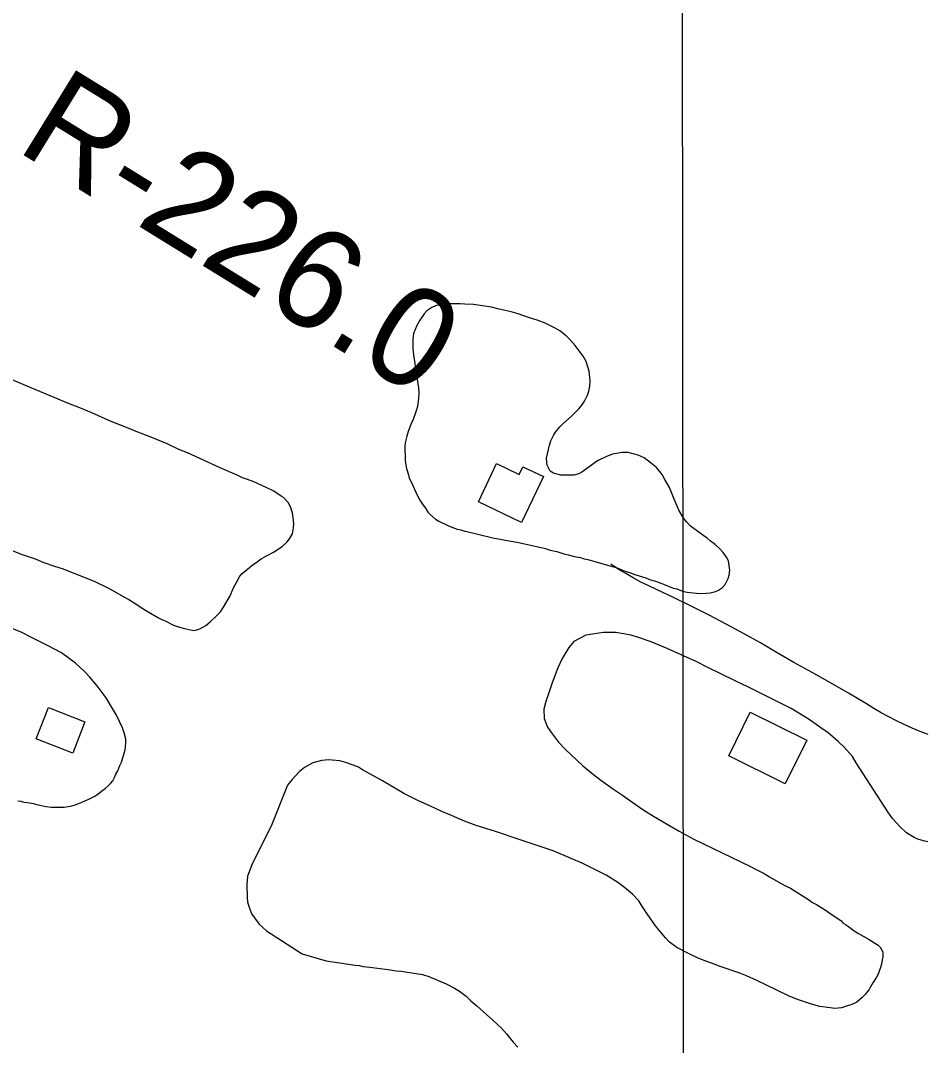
# Model space of a CAD drawing. Extents: x 3297716 to 3335574, y 688621 to 713991.
# Drawn here: x 3317058 to 3317812, y 694852 to 695705 of the extents above; entities that cross this region are included whole.
import ezdxf

# ---------------------------------------------------------------- set-up
doc = ezdxf.new("R2010")
doc.units = 0
for name, color, linetype in [('V-BLDG-OTLN', 7, 'Continuous'), ('V-GRID-MAJR', 7, 'Continuous'), ('V-RIVR-RANG-IDEN', 7, 'Continuous'), ('V-ROAD-CNTR', 7, 'Continuous'), ('V-SITE-VEGE', 7, 'Continuous')]:
    doc.layers.add(name, color=color, linetype=linetype)

msp = doc.modelspace()

# ---------------------------------------------------------------- linework, layer by layer
at = {"layer": 'V-BLDG-OTLN'}
for points in [[(3317475.22, 695287.4), (3317439.22, 695304.55), (3317454.35, 695336.31), (3317473.18, 695327.34), (3317476.25, 695333.76), (3317493.41, 695325.59)], [(3317081.41, 695133.45), (3317111.81, 695121.64), (3317101.63, 695095.43), (3317071.23, 695107.24)], [(3317665.49, 695129.53), (3317712.59, 695106.38), (3317694.67, 695069.95), (3317647.58, 695093.09)]]:
    msp.add_lwpolyline(points, close=True, dxfattribs=at)
at = {"layer": 'V-GRID-MAJR'}
msp.add_spline([(3317610.85, 694015.48), (3317607.77, 697042.82), (3317601.6, 703104.4), (3317595.43, 709166.01), (3317592.34, 712200.26)], degree=3, dxfattribs=at)
at = {"layer": 'V-ROAD-CNTR'}
msp.add_lwpolyline([(3317813.56, 695111.02), (3317806.85, 695113.55), (3317800.22, 695116.26), (3317793.67, 695119.17), (3317787.2, 695122.27), (3317780.83, 695125.55), (3317774.56, 695129.02), (3317768.39, 695132.67), (3317762.33, 695136.5), (3317747.36, 695145.34), (3317732.29, 695154), (3317717.1, 695162.47), (3317701.82, 695170.75), (3317687.91, 695179.02), (3317673.89, 695187.1), (3317659.76, 695194.99), (3317645.52, 695202.69), (3317631.19, 695210.21), (3317616.76, 695217.53), (3317602.23, 695224.66), (3317587.61, 695231.6), (3317581.02, 695234.62), (3317574.52, 695237.84), (3317568.12, 695241.25), (3317561.82, 695244.85), (3317555.64, 695248.64), (3317549.57, 695252.61)], dxfattribs=at)
at = {"layer": 'V-SITE-VEGE'}
for points in [[(3317609.63, 695291.45), (3317606.15, 695297.53), (3317604.79, 695300.84), (3317602.09, 695306.68), (3317598.27, 695316.34), (3317594.51, 695323.19), (3317592.11, 695327.23), (3317587.35, 695333.03), (3317583.42, 695336.53), (3317577.15, 695341.26), (3317572.22, 695343.45), (3317563.95, 695345.57), (3317558.82, 695345.71), (3317550.89, 695344.24), (3317545.81, 695342.32), (3317538.45, 695338.55), (3317525.32, 695329.27), (3317522.79, 695327.92), (3317518.71, 695326.8), (3317511.27, 695326.62), (3317507.92, 695326.8), (3317503.79, 695327.73), (3317501.73, 695328.45), (3317499.12, 695330.19), (3317496.44, 695335), (3317496.12, 695337.56), (3317496.04, 695340.9), (3317498.35, 695351.73), (3317499.56, 695355.35), (3317501.76, 695359.77), (3317503.49, 695362.64), (3317506.98, 695366.82), (3317509.49, 695369.45), (3317516.79, 695375.78), (3317522.81, 695381.83), (3317525.3, 695384.96), (3317527.53, 695388.35), (3317529.98, 695393.29), (3317531.18, 695396.65), (3317532.11, 695400.78), (3317532.27, 695405.15), (3317531.56, 695413.34), (3317528.81, 695421.24), (3317526.39, 695425.8), (3317522.41, 695431.36), (3317519.77, 695434.63), (3317515.29, 695439.66), (3317512.39, 695442.67), (3317506.9, 695446.91), (3317503.26, 695449.13), (3317494.69, 695453.29), (3317488.99, 695455.47), (3317480.2, 695458.09), (3317472.44, 695460.99), (3317466.49, 695462.65), (3317456.68, 695464.98), (3317450.23, 695466.37), (3317440.7, 695467.94), (3317435.29, 695468.59), (3317428.1, 695468.93), (3317423.98, 695469.35), (3317417.83, 695469.2), (3317413.71, 695469.36), (3317407.31, 695468.7), (3317403.49, 695467.58), (3317400.44, 695466.23), (3317396.4, 695463.57), (3317394.15, 695460.95), (3317390.42, 695455.73), (3317387.96, 695451.3), (3317385.29, 695444.57), (3317384.64, 695439.68), (3317384.82, 695431.98), (3317385.19, 695426.85), (3317386.39, 695419.69), (3317387.01, 695415.09), (3317389.43, 695399.49), (3317389.79, 695395.13), (3317389.38, 695390.76), (3317388.51, 695383.81), (3317387.33, 695379.42), (3317384.91, 695372.95), (3317382.96, 695368.79), (3317380.78, 695363.09), (3317379.59, 695359.21), (3317378.44, 695353.54), (3317378.01, 695350.19), (3317378.25, 695339.68), (3317378.58, 695336.6), (3317379.45, 695332.26), (3317381.12, 695326.91), (3317381.69, 695324.36), (3317383.58, 695320.55), (3317388.19, 695310.13), (3317390.6, 695305.83), (3317393.26, 695301.78), (3317395.11, 695299.26), (3317397.25, 695295.97), (3317398.83, 695294.21), (3317403.54, 695290.22), (3317406.41, 695288.48)], [(3317143.72, 695225.77), (3317148.45, 695223.17), (3317154.95, 695219.14), (3317158.7, 695216.52), (3317164.45, 695212.96), (3317172.93, 695207.99), (3317175.68, 695206.58), (3317178.66, 695205.42), (3317185.63, 695201.89), (3317190.59, 695200.29), (3317194.56, 695199.15), (3317202.22, 695197.6), (3317204.92, 695198.16), (3317207.36, 695198.95), (3317212.47, 695201.54), (3317216.09, 695204.57), (3317221.39, 695209.62), (3317224.51, 695213.14), (3317227.13, 695216.89), (3317232.56, 695226.38), (3317235.13, 695232.34), (3317240.8, 695242.57), (3317242.72, 695244.83), (3317248.76, 695249.9), (3317250.68, 695251.66), (3317255.04, 695254.72), (3317258.43, 695257.01), (3317262.32, 695259.32), (3317268.64, 695262.67), (3317275.91, 695267.52), (3317280.25, 695271.31), (3317282.16, 695273.82), (3317284.52, 695278.06), (3317285.39, 695283), (3317285.57, 695286.21), (3317285.19, 695291.61), (3317284.61, 695295.29), (3317282.77, 695300.42), (3317280.96, 695304.07), (3317276.93, 695308.16), (3317275.18, 695309.35), (3317268.93, 695313.39), (3317262.21, 695316.68), (3317252.25, 695321.12), (3317247.03, 695323.21), (3317243.06, 695324.59), (3317238.58, 695326.7), (3317224.41, 695332.77), (3317207.49, 695340.5), (3317197.04, 695345.42), (3317190.08, 695348.21), (3317180.12, 695352.91), (3317166.21, 695358.49), (3317155.77, 695362.43), (3317149.31, 695365.23), (3317133.65, 695371.51), (3317117.49, 695378.51), (3317107.54, 695382.71), (3317098.1, 695386.43), (3317062.31, 695401.34), (3317044.15, 695409.04)], [(3317406.41, 695288.48), (3317413.93, 695284.81), (3317417.04, 695283.6), (3317421.7, 695281.92), (3317424.54, 695281.21), (3317427.91, 695280.01), (3317428.42, 695280.02), (3317451.14, 695274.65), (3317474.08, 695270.31), (3317494.98, 695265.66), (3317498.86, 695264.47), (3317504.54, 695263.32), (3317510.49, 695261.15), (3317514.36, 695260.47), (3317519.01, 695259.04), (3317524.17, 695258.14), (3317527.27, 695257.18), (3317530.37, 695256.48), (3317536.05, 695254.82), (3317546.64, 695251.99), (3317554.66, 695249.61), (3317559.84, 695247.42), (3317565.79, 695245.51), (3317569.41, 695244.05), (3317573.03, 695243.11), (3317578.72, 695241.19), (3317582.61, 695239.74), (3317586.74, 695238.56), (3317593.22, 695236.14), (3317601.25, 695232.73), (3317604.35, 695232.04), (3317609.01, 695230.35), (3317612.88, 695229.41), (3317623.17, 695228.37), (3317628.82, 695228.5), (3317632.15, 695228.84), (3317636.48, 695229.97), (3317639.03, 695231.05), (3317642.31, 695233.19), (3317644.56, 695235.8), (3317647.01, 695240.74), (3317647.97, 695243.58), (3317648.39, 695247.7), (3317647.44, 695255.38), (3317645.83, 695258.42), (3317642.91, 695262.46), (3317640.53, 695265.23), (3317636.34, 695268.98), (3317632.16, 695271.96), (3317629.54, 695274.21), (3317626.93, 695276.2), (3317615.7, 695284.41), (3317612.8, 695287.68), (3317609.63, 695291.45)], [(3317050.5, 695264.2), (3317059.45, 695260.72), (3317070.37, 695257.04), (3317076.83, 695254.48), (3317086.51, 695251.01), (3317092.96, 695248.95), (3317107.61, 695243.39), (3317119.54, 695238.49), (3317131.49, 695232.62), (3317136.48, 695230.03), (3317143.72, 695225.77)], [(3317055.88, 695055.83), (3317058.35, 695055.64), (3317060.83, 695054.71), (3317064.04, 695054.3), (3317068.99, 695053.43), (3317071.46, 695052.75), (3317079.63, 695050.97), (3317083.58, 695050.57), (3317086.29, 695050.63), (3317090.96, 695050.5), (3317094.41, 695050.58), (3317099.56, 695051.44), (3317102.98, 695052.25), (3317106.65, 695053.57), (3317111.77, 695055.66), (3317115.18, 695057.22), (3317120.04, 695059.79), (3317122.95, 695061.58), (3317126.82, 695064.63), (3317128.76, 695065.91), (3317131.41, 695068.43), (3317133.09, 695070.19), (3317135, 695072.45), (3317136.18, 695074.7), (3317137.58, 695077.93), (3317139.24, 695080.68), (3317140.86, 695085.14), (3317142.27, 695087.89), (3317144.56, 695095.32), (3317145.23, 695098.29), (3317145.84, 695103.72), (3317145.76, 695107.17), (3317144.41, 695112.31), (3317143.08, 695116.46), (3317138.16, 695126.93), (3317133.81, 695133.96), (3317129.45, 695141.49), (3317122.08, 695151.41), (3317116, 695158.65), (3317111.45, 695163.47), (3317103.91, 695170.44), (3317092.39, 695178.78), (3317080.67, 695185.15), (3317067.96, 695191.5), (3317059.25, 695195.73), (3317046.07, 695201.32)], [(3317639.85, 695162.01), (3317630.66, 695166.34), (3317619.92, 695171.85), (3317615.62, 695173.87), (3317602.45, 695179.62), (3317596.32, 695182.51), (3317589.58, 695185.39), (3317583.16, 695187.96), (3317573.38, 695191.37), (3317566.35, 695193.63), (3317553.57, 695195.76), (3317543.26, 695195.82), (3317528.76, 695193.66), (3317518.58, 695188.27), (3317514.45, 695183.32), (3317508.9, 695174.1), (3317505.45, 695166.43), (3317500.58, 695153.89), (3317497.75, 695145.64), (3317495.49, 695138.31), (3317493.83, 695131.91), (3317494, 695124.33), (3317496.9, 695117.12), (3317500.04, 695112.34), (3317505.99, 695104.6), (3317511.58, 695098.67), (3317525.85, 695085.06), (3317535.11, 695077.7), (3317541.29, 695072.99), (3317551.77, 695065.35), (3317559.17, 695060.38), (3317569.65, 695053.04), (3317577.04, 695048.06), (3317585.04, 695043.09), (3317597.65, 695035.51), (3317606.25, 695030.56), (3317618.53, 695023.87), (3317665.14, 695001.32), (3317669.75, 694999), (3317677.11, 694995.23), (3317681.42, 694992.6), (3317690.63, 694987.36), (3317695.85, 694984.45), (3317698.92, 694983.01), (3317714.92, 694973.08), (3317716.77, 694971.6), (3317720.76, 694969.58), (3317725.08, 694966.65), (3317728.76, 694964.61), (3317732.78, 694961.37), (3317740.79, 694956.1), (3317742.95, 694954.03), (3317744.8, 694952.86), (3317747.27, 694951.1), (3317751.9, 694947.57), (3317755.58, 694945.53), (3317764.5, 694940.29), (3317771.88, 694935.61), (3317773.74, 694934.14), (3317775.95, 694930.25), (3317775.75, 694926), (3317775.2, 694923.56), (3317774.68, 694919.91), (3317773.83, 694917.16), (3317771.55, 694911.05), (3317770.68, 694909.21), (3317767.46, 694904.28), (3317765.43, 694900.59), (3317764.56, 694898.75), (3317762.79, 694896.89), (3317761.32, 694895.04), (3317758.65, 694892.25), (3317754.2, 694888.2), (3317750, 694886.28), (3317745.48, 694884.97), (3317741.57, 694883.66), (3317735.83, 694882.92), (3317731.88, 694883.44), (3317723.36, 694884.75), (3317716.34, 694886.71), (3317705.65, 694890.1), (3317698, 694893.25), (3317686.96, 694898.45), (3317671.01, 694906.26), (3317662.43, 694910.3), (3317656.93, 694912.3), (3317640.42, 694917.97), (3317635.52, 694919.98), (3317627.27, 694922.82), (3317622.07, 694924.82), (3317615.32, 694928.3), (3317604.28, 694933.8), (3317598.41, 694938.21), (3317594.99, 694941.77), (3317586.57, 694951.88), (3317579.67, 694961.72), (3317575.27, 694968.29), (3317572.75, 694972.47), (3317567.46, 694978.11), (3317560.96, 694983.72), (3317555.41, 694987.83)], [(3317813.22, 695021.77), (3317809.56, 695022.59), (3317804.98, 695024), (3317801.92, 695025.14), (3317797.62, 695027.77), (3317795.45, 695029.23), (3317790.19, 695034.26), (3317783.96, 695041.09), (3317779.89, 695046.75), (3317753.77, 695087.37), (3317750.62, 695092.76), (3317743.77, 695100.48), (3317738.8, 695105.21), (3317730.45, 695112.29), (3317724.29, 695116.39), (3317714.43, 695123.44), (3317699.66, 695132.49), (3317663.46, 695150.74), (3317653.96, 695155.06), (3317639.85, 695162.01)], [(3317555.41, 694987.83), (3317545.56, 694993.96), (3317525.63, 695003.81), (3317516.44, 695007.83), (3317501.44, 695014.15), (3317474.86, 695022.93), (3317453.46, 695030.31), (3317437.27, 695035.39), (3317427.79, 695038.8), (3317416.77, 695043.7), (3317408.81, 695046.84), (3317399.31, 695051.47), (3317388.89, 695056.08), (3317377.23, 695061.87), (3317359.4, 695072.36), (3317342.81, 695081.68), (3317339.43, 695083.72), (3317329.64, 695087.43), (3317323.85, 695089.11), (3317314.43, 695089.8), (3317308.98, 695089.37), (3317301.45, 695087.38), (3317294.57, 695083.58), (3317290.4, 695080.14), (3317283.89, 695073.32), (3317280.36, 695068.69), (3317266.91, 695034.72), (3317251.26, 695004.04), (3317246.97, 694993.03), (3317246.53, 694986.04), (3317246.78, 694975.44), (3317247.17, 694971.81), (3317247.52, 694969.7), (3317248.48, 694967.29), (3317249.79, 694963.38), (3317250.74, 694961.58), (3317256.7, 694953.24), (3317262.89, 694947.62), (3317292.69, 694928.6), (3317312.52, 694922.56), (3317336.59, 694919.16), (3317340.3, 694918.75), (3317343.27, 694917.84), (3317348.94, 694917.48), (3317357.59, 694916.2), (3317364.25, 694915.37), (3317370.92, 694914.3), (3317375.11, 694914.15), (3317392.66, 694911.36), (3317398.11, 694909.52), (3317412.53, 694903.46), (3317419.26, 694899.93), (3317423.51, 694897.32), (3317429.02, 694893.26), (3317433.05, 694889.42), (3317438.07, 694885.1), (3317445.87, 694877.9), (3317451.39, 694873.35), (3317458.45, 694866.63), (3317462.74, 694861.81), (3317468.32, 694855.04), (3317472.11, 694850.7)]]:
    msp.add_lwpolyline(points, dxfattribs=at)

# ---------------------------------------------------------------- texts
at = {"layer": 'V-RIVR-RANG-IDEN'}
msp.add_text('R-226.0', height=83, rotation=328.33182, dxfattribs=at).set_placement((3317053.05, 695597.72))

doc.saveas('drawing.dxf')
